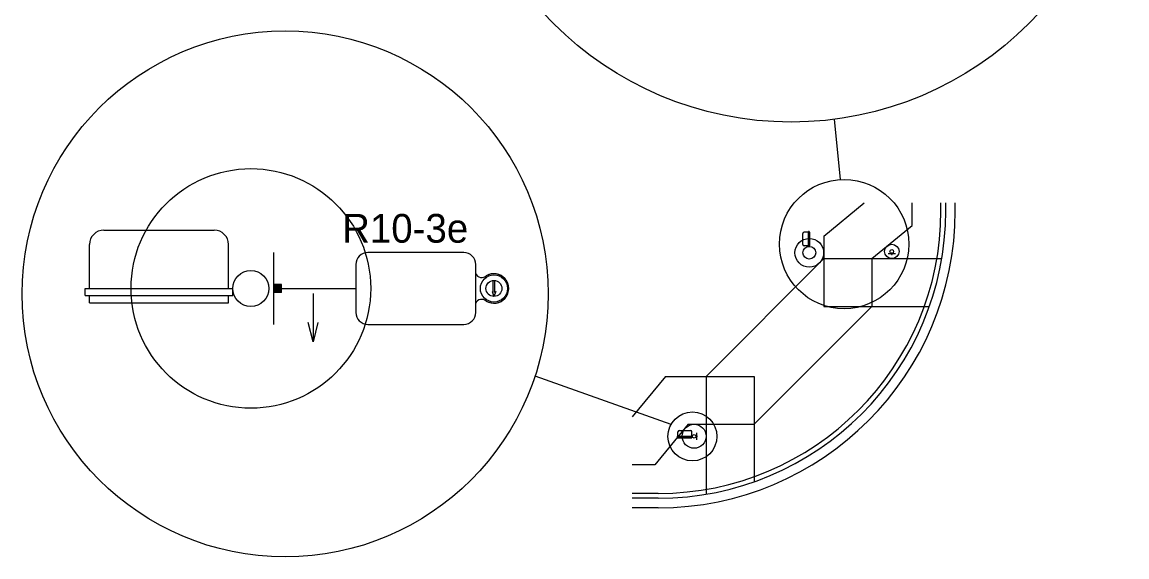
# Model space of a CAD drawing. Extents: x 1695551 to 1695718, y 544410 to 544516.
# Drawn here: x 1695643.15 to 1695671.96, y 544427.28 to 544441.23 of the extents above; entities that cross this region are included whole.
import ezdxf

# ---------------------------------------------------------------- set-up
doc = ezdxf.new("R2010")
doc.units = 0
doc.layers.add('T_Drafting', color=7, linetype='Continuous')

msp = doc.modelspace()

# ---------------------------------------------------------------- linework, layer by layer
at = {"layer": 'T_Drafting'}
for p, q in [((1695664.488, 544437.122), (1695664.339, 544438.696)), ((1695664.057, 544435.649), (1695665.107, 544436.512)), ((1695666.361, 544435.925), (1695666.361, 544436.512)), ((1695667.111, 544436.309), (1695667.111, 544436.512)), ((1695667.236, 544436.309), (1695667.236, 544436.512)), ((1695667.486, 544436.309), (1695667.486, 544436.512)), ((1695665.307, 544435.059), (1695666.361, 544435.925)), ((1695645.28, 544435.803), (1695648.155, 544435.803)), ((1695663.506, 544435.429), (1695663.506, 544435.716)), ((1695663.658, 544435.754), (1695663.543, 544435.754)), ((1695663.658, 544435.38), (1695663.658, 544435.765)), ((1695663.677, 544435.765), (1695663.658, 544435.765)), ((1695663.677, 544435.38), (1695663.677, 544435.765)), ((1695663.696, 544435.754), (1695663.677, 544435.754)), ((1695663.696, 544435.391), (1695663.696, 544435.754)), ((1695664.057, 544435.649), (1695664.057, 544433.809)), ((1695644.905, 544434.282), (1695644.905, 544435.428)), ((1695648.53, 544434.282), (1695648.53, 544435.428)), ((1695663.658, 544435.391), (1695663.543, 544435.391)), ((1695663.677, 544435.38), (1695663.658, 544435.38)), ((1695663.696, 544435.391), (1695663.677, 544435.391)), ((1695649.707, 544435.22), (1695649.707, 544433.345)), ((1695654.666, 544435.22), (1695652.162, 544435.22)), ((1695664.057, 544435.059), (1695660.986, 544431.987)), ((1695664.057, 544435.059), (1695667.131, 544435.059)), ((1695665.307, 544435.059), (1695665.307, 544433.809)), ((1695665.924, 544435.187), (1695665.737, 544435.187)), ((1695665.82, 544435.166), (1695665.82, 544435.187)), ((1695665.82, 544435.166), (1695665.841, 544435.187)), ((1695665.82, 544435.166), (1695665.84, 544435.187)), ((1695665.82, 544435.167), (1695665.84, 544435.187)), ((1695665.82, 544435.167), (1695665.84, 544435.187)), ((1695665.82, 544435.167), (1695665.839, 544435.187)), ((1695665.82, 544435.168), (1695665.839, 544435.187)), ((1695665.82, 544435.168), (1695665.839, 544435.187)), ((1695665.82, 544435.168), (1695665.838, 544435.187)), ((1695665.82, 544435.169), (1695665.838, 544435.187)), ((1695665.82, 544435.169), (1695665.838, 544435.187)), ((1695665.82, 544435.169), (1695665.837, 544435.187)), ((1695665.82, 544435.17), (1695665.837, 544435.187)), ((1695665.82, 544435.17), (1695665.837, 544435.187)), ((1695665.82, 544435.171), (1695665.836, 544435.187)), ((1695665.82, 544435.171), (1695665.836, 544435.187)), ((1695665.82, 544435.171), (1695665.835, 544435.187)), ((1695665.82, 544435.172), (1695665.835, 544435.187)), ((1695665.82, 544435.172), (1695665.835, 544435.187)), ((1695665.82, 544435.172), (1695665.834, 544435.187)), ((1695665.82, 544435.173), (1695665.834, 544435.187)), ((1695665.82, 544435.173), (1695665.834, 544435.187)), ((1695665.82, 544435.173), (1695665.833, 544435.187)), ((1695665.82, 544435.174), (1695665.833, 544435.187)), ((1695665.82, 544435.174), (1695665.833, 544435.187)), ((1695665.82, 544435.174), (1695665.832, 544435.187)), ((1695665.82, 544435.175), (1695665.832, 544435.187)), ((1695665.82, 544435.175), (1695665.832, 544435.187)), ((1695665.82, 544435.175), (1695665.831, 544435.187)), ((1695665.82, 544435.176), (1695665.831, 544435.187)), ((1695665.82, 544435.176), (1695665.831, 544435.187)), ((1695665.82, 544435.177), (1695665.83, 544435.187)), ((1695665.82, 544435.177), (1695665.83, 544435.187)), ((1695665.82, 544435.177), (1695665.829, 544435.187)), ((1695665.82, 544435.178), (1695665.829, 544435.187)), ((1695665.82, 544435.178), (1695665.829, 544435.187)), ((1695665.82, 544435.178), (1695665.828, 544435.187)), ((1695665.82, 544435.179), (1695665.828, 544435.187)), ((1695665.82, 544435.179), (1695665.828, 544435.187)), ((1695665.82, 544435.179), (1695665.827, 544435.187)), ((1695665.82, 544435.18), (1695665.827, 544435.187)), ((1695665.82, 544435.18), (1695665.827, 544435.187)), ((1695665.82, 544435.18), (1695665.826, 544435.187)), ((1695665.82, 544435.181), (1695665.826, 544435.187)), ((1695665.82, 544435.181), (1695665.826, 544435.187)), ((1695665.82, 544435.182), (1695665.825, 544435.187)), ((1695665.82, 544435.182), (1695665.825, 544435.187)), ((1695665.82, 544435.182), (1695665.824, 544435.187)), ((1695665.82, 544435.183), (1695665.824, 544435.187)), ((1695665.82, 544435.183), (1695665.824, 544435.187)), ((1695665.82, 544435.183), (1695665.823, 544435.187)), ((1695665.82, 544435.184), (1695665.823, 544435.187)), ((1695665.82, 544435.184), (1695665.823, 544435.187)), ((1695665.82, 544435.184), (1695665.822, 544435.187)), ((1695665.82, 544435.185), (1695665.822, 544435.187)), ((1695665.82, 544435.185), (1695665.822, 544435.187)), ((1695665.82, 544435.185), (1695665.821, 544435.187)), ((1695665.82, 544435.186), (1695665.821, 544435.187)), ((1695665.82, 544435.186), (1695665.821, 544435.187)), ((1695665.82, 544435.186), (1695665.82, 544435.187)), ((1695665.82, 544435.166), (1695665.841, 544435.186)), ((1695665.82, 544435.166), (1695665.841, 544435.166)), ((1695665.821, 544435.166), (1695665.841, 544435.186)), ((1695665.821, 544435.166), (1695665.841, 544435.186)), ((1695665.821, 544435.166), (1695665.841, 544435.185)), ((1695665.822, 544435.166), (1695665.841, 544435.185)), ((1695665.822, 544435.166), (1695665.841, 544435.185)), ((1695665.822, 544435.166), (1695665.841, 544435.184)), ((1695665.823, 544435.166), (1695665.841, 544435.184)), ((1695665.823, 544435.166), (1695665.841, 544435.184)), ((1695665.823, 544435.166), (1695665.841, 544435.183)), ((1695665.824, 544435.166), (1695665.841, 544435.183)), ((1695665.824, 544435.166), (1695665.841, 544435.183)), ((1695665.825, 544435.166), (1695665.841, 544435.182)), ((1695665.825, 544435.166), (1695665.841, 544435.182)), ((1695665.825, 544435.166), (1695665.841, 544435.181)), ((1695665.826, 544435.166), (1695665.841, 544435.181)), ((1695665.826, 544435.166), (1695665.841, 544435.181)), ((1695665.826, 544435.166), (1695665.841, 544435.18)), ((1695665.827, 544435.166), (1695665.841, 544435.18)), ((1695665.827, 544435.166), (1695665.841, 544435.18)), ((1695665.827, 544435.166), (1695665.841, 544435.179)), ((1695665.828, 544435.166), (1695665.841, 544435.179)), ((1695665.828, 544435.166), (1695665.841, 544435.179)), ((1695665.828, 544435.166), (1695665.841, 544435.178)), ((1695665.829, 544435.166), (1695665.841, 544435.178)), ((1695665.829, 544435.166), (1695665.841, 544435.178)), ((1695665.829, 544435.166), (1695665.841, 544435.177)), ((1695665.83, 544435.166), (1695665.841, 544435.177)), ((1695665.83, 544435.166), (1695665.841, 544435.177)), ((1695665.831, 544435.166), (1695665.841, 544435.176)), ((1695665.831, 544435.166), (1695665.841, 544435.176)), ((1695665.831, 544435.166), (1695665.841, 544435.175)), ((1695665.832, 544435.166), (1695665.841, 544435.175)), ((1695665.832, 544435.166), (1695665.841, 544435.175)), ((1695665.832, 544435.166), (1695665.841, 544435.174)), ((1695665.833, 544435.166), (1695665.841, 544435.174)), ((1695665.833, 544435.166), (1695665.841, 544435.174)), ((1695665.833, 544435.166), (1695665.841, 544435.173)), ((1695665.834, 544435.166), (1695665.841, 544435.173)), ((1695665.834, 544435.166), (1695665.841, 544435.173)), ((1695665.834, 544435.166), (1695665.841, 544435.172)), ((1695665.835, 544435.166), (1695665.841, 544435.172)), ((1695665.835, 544435.166), (1695665.841, 544435.172)), ((1695665.835, 544435.166), (1695665.841, 544435.171)), ((1695665.836, 544435.166), (1695665.841, 544435.171)), ((1695665.836, 544435.166), (1695665.841, 544435.171)), ((1695665.837, 544435.166), (1695665.841, 544435.17)), ((1695665.837, 544435.166), (1695665.841, 544435.17)), ((1695665.837, 544435.166), (1695665.841, 544435.169)), ((1695665.838, 544435.166), (1695665.841, 544435.169)), ((1695665.838, 544435.166), (1695665.841, 544435.169)), ((1695665.838, 544435.166), (1695665.841, 544435.168)), ((1695665.839, 544435.166), (1695665.841, 544435.168)), ((1695665.839, 544435.166), (1695665.841, 544435.168)), ((1695665.839, 544435.166), (1695665.841, 544435.167)), ((1695665.84, 544435.166), (1695665.841, 544435.167)), ((1695665.84, 544435.166), (1695665.841, 544435.167)), ((1695665.84, 544435.166), (1695665.841, 544435.166)), ((1695665.841, 544435.166), (1695665.841, 544435.187)), ((1695665.841, 544435.166), (1695665.841, 544435.166)), ((1695651.849, 544434.907), (1695651.849, 544433.657)), ((1695654.978, 544433.657), (1695654.978, 544434.907)), ((1695649.915, 544434.386), (1695649.707, 544434.386)), ((1695649.707, 544434.179), (1695649.914, 544434.386)), ((1695649.707, 544434.182), (1695649.911, 544434.386)), ((1695649.707, 544434.186), (1695649.907, 544434.386)), ((1695649.707, 544434.189), (1695649.904, 544434.386)), ((1695649.707, 544434.193), (1695649.9, 544434.386)), ((1695649.707, 544434.197), (1695649.897, 544434.386)), ((1695649.707, 544434.2), (1695649.893, 544434.386)), ((1695649.707, 544434.204), (1695649.89, 544434.386)), ((1695649.707, 544434.207), (1695649.886, 544434.386)), ((1695649.707, 544434.211), (1695649.883, 544434.386)), ((1695649.707, 544434.214), (1695649.879, 544434.386)), ((1695649.707, 544434.218), (1695649.876, 544434.386)), ((1695649.707, 544434.221), (1695649.872, 544434.386)), ((1695649.707, 544434.225), (1695649.869, 544434.386)), ((1695649.707, 544434.228), (1695649.865, 544434.386)), ((1695649.707, 544434.232), (1695649.861, 544434.386)), ((1695649.707, 544434.235), (1695649.858, 544434.386)), ((1695649.707, 544434.239), (1695649.854, 544434.386)), ((1695649.707, 544434.243), (1695649.851, 544434.386)), ((1695649.707, 544434.246), (1695649.847, 544434.386)), ((1695649.707, 544434.25), (1695649.844, 544434.386)), ((1695649.707, 544434.253), (1695649.84, 544434.386)), ((1695649.707, 544434.257), (1695649.837, 544434.386)), ((1695649.707, 544434.26), (1695649.833, 544434.386)), ((1695649.707, 544434.264), (1695649.83, 544434.386)), ((1695649.707, 544434.267), (1695649.826, 544434.386)), ((1695649.707, 544434.271), (1695649.823, 544434.386)), ((1695649.707, 544434.274), (1695649.819, 544434.386)), ((1695649.707, 544434.278), (1695649.815, 544434.386)), ((1695649.707, 544434.281), (1695649.812, 544434.386)), ((1695649.707, 544434.285), (1695649.808, 544434.386)), ((1695649.707, 544434.288), (1695649.805, 544434.386)), ((1695649.707, 544434.292), (1695649.801, 544434.386)), ((1695649.707, 544434.296), (1695649.798, 544434.386)), ((1695649.707, 544434.299), (1695649.794, 544434.386)), ((1695649.707, 544434.303), (1695649.791, 544434.386)), ((1695649.707, 544434.306), (1695649.787, 544434.386)), ((1695649.707, 544434.31), (1695649.784, 544434.386)), ((1695649.707, 544434.313), (1695649.78, 544434.386)), ((1695649.707, 544434.317), (1695649.777, 544434.386)), ((1695649.707, 544434.32), (1695649.773, 544434.386)), ((1695649.707, 544434.324), (1695649.77, 544434.386)), ((1695649.707, 544434.327), (1695649.766, 544434.386)), ((1695649.707, 544434.331), (1695649.762, 544434.386)), ((1695649.707, 544434.334), (1695649.759, 544434.386)), ((1695649.707, 544434.338), (1695649.755, 544434.386)), ((1695649.707, 544434.342), (1695649.752, 544434.386)), ((1695649.707, 544434.345), (1695649.748, 544434.386)), ((1695649.707, 544434.349), (1695649.745, 544434.386)), ((1695649.707, 544434.352), (1695649.741, 544434.386)), ((1695649.707, 544434.356), (1695649.738, 544434.386)), ((1695649.707, 544434.359), (1695649.734, 544434.386)), ((1695649.707, 544434.363), (1695649.731, 544434.386)), ((1695649.707, 544434.366), (1695649.727, 544434.386)), ((1695649.707, 544434.37), (1695649.724, 544434.386)), ((1695649.707, 544434.373), (1695649.72, 544434.386)), ((1695649.707, 544434.377), (1695649.716, 544434.386)), ((1695649.707, 544434.38), (1695649.713, 544434.386)), ((1695649.707, 544434.384), (1695649.709, 544434.386)), ((1695649.71, 544434.178), (1695649.915, 544434.384)), ((1695649.713, 544434.178), (1695649.915, 544434.38)), ((1695649.915, 544434.178), (1695649.915, 544434.386)), ((1695655.434, 544434.489), (1695655.472, 544434.489)), ((1695655.434, 544434.176), (1695655.434, 544434.489)), ((1695655.472, 544434.176), (1695655.472, 544434.489)), ((1695644.79, 544434.282), (1695648.644, 544434.282)), ((1695644.79, 544434.095), (1695644.79, 544434.282)), ((1695644.79, 544434.095), (1695648.644, 544434.095)), ((1695644.905, 544433.907), (1695644.905, 544434.095)), ((1695648.53, 544433.907), (1695648.53, 544434.095)), ((1695648.644, 544434.095), (1695648.644, 544434.282)), ((1695649.915, 544434.178), (1695649.707, 544434.178)), ((1695649.717, 544434.178), (1695649.915, 544434.377)), ((1695649.72, 544434.178), (1695649.915, 544434.373)), ((1695649.724, 544434.178), (1695649.915, 544434.37)), ((1695649.727, 544434.178), (1695649.915, 544434.366)), ((1695649.731, 544434.178), (1695649.915, 544434.362)), ((1695649.734, 544434.178), (1695649.915, 544434.359)), ((1695649.738, 544434.178), (1695649.915, 544434.355)), ((1695649.741, 544434.178), (1695649.915, 544434.352)), ((1695649.745, 544434.178), (1695649.915, 544434.348)), ((1695649.749, 544434.178), (1695649.915, 544434.345)), ((1695649.752, 544434.178), (1695649.915, 544434.341)), ((1695649.756, 544434.178), (1695649.915, 544434.338)), ((1695649.759, 544434.178), (1695649.915, 544434.334)), ((1695649.763, 544434.178), (1695649.915, 544434.331)), ((1695649.766, 544434.178), (1695649.915, 544434.327)), ((1695649.77, 544434.178), (1695649.915, 544434.324)), ((1695649.773, 544434.178), (1695649.915, 544434.32)), ((1695649.777, 544434.178), (1695649.915, 544434.317)), ((1695649.78, 544434.178), (1695649.915, 544434.313)), ((1695649.784, 544434.178), (1695649.915, 544434.309)), ((1695649.787, 544434.178), (1695649.915, 544434.306)), ((1695649.791, 544434.178), (1695649.915, 544434.302)), ((1695649.795, 544434.178), (1695649.915, 544434.299)), ((1695649.798, 544434.178), (1695649.915, 544434.295)), ((1695649.802, 544434.178), (1695649.915, 544434.292)), ((1695649.805, 544434.178), (1695649.915, 544434.288)), ((1695649.809, 544434.178), (1695649.915, 544434.285)), ((1695649.812, 544434.178), (1695649.915, 544434.281)), ((1695649.816, 544434.178), (1695649.915, 544434.278)), ((1695649.819, 544434.178), (1695649.915, 544434.274)), ((1695649.823, 544434.178), (1695649.915, 544434.271)), ((1695649.826, 544434.178), (1695649.915, 544434.267)), ((1695649.83, 544434.178), (1695649.915, 544434.263)), ((1695649.833, 544434.178), (1695649.915, 544434.26)), ((1695649.837, 544434.178), (1695649.915, 544434.256)), ((1695649.84, 544434.178), (1695649.915, 544434.253)), ((1695649.844, 544434.178), (1695649.915, 544434.249)), ((1695649.848, 544434.178), (1695649.915, 544434.246)), ((1695649.851, 544434.178), (1695649.915, 544434.242)), ((1695649.855, 544434.178), (1695649.915, 544434.239)), ((1695649.858, 544434.178), (1695649.915, 544434.235)), ((1695649.862, 544434.178), (1695649.915, 544434.232)), ((1695649.865, 544434.178), (1695649.915, 544434.228)), ((1695649.869, 544434.178), (1695649.915, 544434.225)), ((1695649.872, 544434.178), (1695649.915, 544434.221)), ((1695649.876, 544434.178), (1695649.915, 544434.218)), ((1695649.879, 544434.178), (1695649.915, 544434.214)), ((1695649.883, 544434.178), (1695649.915, 544434.21)), ((1695649.886, 544434.178), (1695649.915, 544434.207)), ((1695649.89, 544434.178), (1695649.915, 544434.203)), ((1695649.894, 544434.178), (1695649.915, 544434.2)), ((1695649.897, 544434.178), (1695649.915, 544434.196)), ((1695649.901, 544434.178), (1695649.915, 544434.193)), ((1695649.904, 544434.178), (1695649.915, 544434.189)), ((1695649.908, 544434.178), (1695649.915, 544434.186)), ((1695649.911, 544434.178), (1695649.915, 544434.182)), ((1695649.915, 544434.282), (1695651.849, 544434.282)), ((1695649.915, 544434.178), (1695649.915, 544434.179)), ((1695650.734, 544434.149), (1695650.734, 544432.891)), ((1695655.403, 544434.201), (1695655.453, 544434.074)), ((1695655.434, 544434.176), (1695655.403, 544434.201)), ((1695655.503, 544434.201), (1695655.453, 544434.074)), ((1695655.503, 544434.201), (1695655.472, 544434.176)), ((1695644.905, 544433.907), (1695648.53, 544433.907)), ((1695665.307, 544433.809), (1695662.236, 544430.737)), ((1695664.057, 544433.809), (1695666.807, 544433.809)), ((1695652.162, 544433.345), (1695654.666, 544433.345)), ((1695660.072, 544430.731), (1695656.524, 544431.995)), ((1695659.929, 544431.987), (1695659.062, 544430.934)), ((1695659.929, 544431.987), (1695662.236, 544431.987)), ((1695660.986, 544431.987), (1695660.986, 544428.913)), ((1695662.236, 544431.987), (1695662.236, 544429.237)), ((1695660.52, 544430.737), (1695659.653, 544429.684)), ((1695660.52, 544430.737), (1695662.236, 544430.737)), ((1695660.241, 544430.425), (1695660.627, 544430.425)), ((1695660.241, 544430.406), (1695660.241, 544430.425)), ((1695660.241, 544430.406), (1695660.627, 544430.406)), ((1695660.253, 544430.425), (1695660.253, 544430.54)), ((1695660.253, 544430.387), (1695660.253, 544430.406)), ((1695660.253, 544430.387), (1695660.615, 544430.387)), ((1695660.29, 544430.577), (1695660.578, 544430.577)), ((1695660.615, 544430.425), (1695660.615, 544430.54)), ((1695660.615, 544430.387), (1695660.615, 544430.406)), ((1695660.627, 544430.406), (1695660.627, 544430.425)), ((1695660.733, 544430.519), (1695660.733, 544430.331)), ((1695660.754, 544430.435), (1695660.733, 544430.435)), ((1695660.733, 544430.415), (1695660.754, 544430.435)), ((1695660.733, 544430.415), (1695660.754, 544430.435)), ((1695660.733, 544430.415), (1695660.754, 544430.435)), ((1695660.733, 544430.415), (1695660.753, 544430.435)), ((1695660.733, 544430.415), (1695660.753, 544430.435)), ((1695660.733, 544430.416), (1695660.753, 544430.435)), ((1695660.733, 544430.416), (1695660.752, 544430.435)), ((1695660.733, 544430.416), (1695660.752, 544430.435)), ((1695660.733, 544430.417), (1695660.751, 544430.435)), ((1695660.733, 544430.417), (1695660.751, 544430.435)), ((1695660.733, 544430.417), (1695660.751, 544430.435)), ((1695660.733, 544430.418), (1695660.75, 544430.435)), ((1695660.733, 544430.418), (1695660.75, 544430.435)), ((1695660.733, 544430.419), (1695660.75, 544430.435)), ((1695660.733, 544430.419), (1695660.749, 544430.435)), ((1695660.733, 544430.419), (1695660.749, 544430.435)), ((1695660.733, 544430.42), (1695660.749, 544430.435)), ((1695660.733, 544430.42), (1695660.748, 544430.435)), ((1695660.733, 544430.42), (1695660.748, 544430.435)), ((1695660.733, 544430.421), (1695660.748, 544430.435)), ((1695660.733, 544430.421), (1695660.747, 544430.435)), ((1695660.733, 544430.421), (1695660.747, 544430.435)), ((1695660.733, 544430.422), (1695660.747, 544430.435)), ((1695660.733, 544430.422), (1695660.746, 544430.435)), ((1695660.733, 544430.422), (1695660.746, 544430.435)), ((1695660.733, 544430.423), (1695660.745, 544430.435)), ((1695660.733, 544430.423), (1695660.745, 544430.435)), ((1695660.733, 544430.423), (1695660.745, 544430.435)), ((1695660.733, 544430.424), (1695660.744, 544430.435)), ((1695660.733, 544430.424), (1695660.744, 544430.435)), ((1695660.733, 544430.425), (1695660.744, 544430.435)), ((1695660.733, 544430.425), (1695660.743, 544430.435)), ((1695660.733, 544430.425), (1695660.743, 544430.435)), ((1695660.733, 544430.426), (1695660.743, 544430.435)), ((1695660.733, 544430.426), (1695660.742, 544430.435)), ((1695660.733, 544430.426), (1695660.742, 544430.435)), ((1695660.733, 544430.427), (1695660.742, 544430.435)), ((1695660.733, 544430.427), (1695660.741, 544430.435)), ((1695660.733, 544430.427), (1695660.741, 544430.435)), ((1695660.733, 544430.428), (1695660.741, 544430.435)), ((1695660.733, 544430.428), (1695660.74, 544430.435)), ((1695660.733, 544430.428), (1695660.74, 544430.435)), ((1695660.733, 544430.429), (1695660.739, 544430.435)), ((1695660.733, 544430.429), (1695660.739, 544430.435)), ((1695660.733, 544430.429), (1695660.739, 544430.435)), ((1695660.733, 544430.43), (1695660.738, 544430.435)), ((1695660.733, 544430.43), (1695660.738, 544430.435)), ((1695660.733, 544430.431), (1695660.738, 544430.435)), ((1695660.733, 544430.431), (1695660.737, 544430.435)), ((1695660.733, 544430.431), (1695660.737, 544430.435)), ((1695660.733, 544430.432), (1695660.737, 544430.435)), ((1695660.733, 544430.432), (1695660.736, 544430.435)), ((1695660.733, 544430.432), (1695660.736, 544430.435)), ((1695660.733, 544430.433), (1695660.736, 544430.435)), ((1695660.733, 544430.433), (1695660.735, 544430.435)), ((1695660.733, 544430.433), (1695660.735, 544430.435)), ((1695660.733, 544430.434), (1695660.735, 544430.435)), ((1695660.733, 544430.434), (1695660.734, 544430.435)), ((1695660.733, 544430.434), (1695660.734, 544430.435)), ((1695660.733, 544430.435), (1695660.733, 544430.435)), ((1695660.733, 544430.435), (1695660.733, 544430.435)), ((1695660.754, 544430.415), (1695660.733, 544430.415)), ((1695660.734, 544430.415), (1695660.754, 544430.434)), ((1695660.734, 544430.415), (1695660.754, 544430.434)), ((1695660.735, 544430.415), (1695660.754, 544430.434)), ((1695660.735, 544430.415), (1695660.754, 544430.433)), ((1695660.735, 544430.415), (1695660.754, 544430.433)), ((1695660.736, 544430.415), (1695660.754, 544430.433)), ((1695660.736, 544430.415), (1695660.754, 544430.432)), ((1695660.736, 544430.415), (1695660.754, 544430.432)), ((1695660.737, 544430.415), (1695660.754, 544430.432)), ((1695660.737, 544430.415), (1695660.754, 544430.431)), ((1695660.737, 544430.415), (1695660.754, 544430.431)), ((1695660.738, 544430.415), (1695660.754, 544430.431)), ((1695660.738, 544430.415), (1695660.754, 544430.43)), ((1695660.738, 544430.415), (1695660.754, 544430.43)), ((1695660.739, 544430.415), (1695660.754, 544430.429)), ((1695660.739, 544430.415), (1695660.754, 544430.429)), ((1695660.739, 544430.415), (1695660.754, 544430.429)), ((1695660.74, 544430.415), (1695660.754, 544430.428)), ((1695660.74, 544430.415), (1695660.754, 544430.428)), ((1695660.741, 544430.415), (1695660.754, 544430.428)), ((1695660.741, 544430.415), (1695660.754, 544430.427)), ((1695660.741, 544430.415), (1695660.754, 544430.427)), ((1695660.742, 544430.415), (1695660.754, 544430.427)), ((1695660.742, 544430.415), (1695660.754, 544430.426)), ((1695660.742, 544430.415), (1695660.754, 544430.426)), ((1695660.743, 544430.415), (1695660.754, 544430.426)), ((1695660.743, 544430.415), (1695660.754, 544430.425)), ((1695660.743, 544430.415), (1695660.754, 544430.425)), ((1695660.744, 544430.415), (1695660.754, 544430.424)), ((1695660.744, 544430.415), (1695660.754, 544430.424)), ((1695660.744, 544430.415), (1695660.754, 544430.424)), ((1695660.745, 544430.415), (1695660.754, 544430.423)), ((1695660.745, 544430.415), (1695660.754, 544430.423)), ((1695660.745, 544430.415), (1695660.754, 544430.423)), ((1695660.746, 544430.415), (1695660.754, 544430.422)), ((1695660.746, 544430.415), (1695660.754, 544430.422)), ((1695660.747, 544430.415), (1695660.754, 544430.422)), ((1695660.747, 544430.415), (1695660.754, 544430.421)), ((1695660.747, 544430.415), (1695660.754, 544430.421)), ((1695660.748, 544430.415), (1695660.754, 544430.421)), ((1695660.748, 544430.415), (1695660.754, 544430.42)), ((1695660.748, 544430.415), (1695660.754, 544430.42)), ((1695660.749, 544430.415), (1695660.754, 544430.42)), ((1695660.749, 544430.415), (1695660.754, 544430.419)), ((1695660.749, 544430.415), (1695660.754, 544430.419)), ((1695660.75, 544430.415), (1695660.754, 544430.418)), ((1695660.75, 544430.415), (1695660.754, 544430.418)), ((1695660.75, 544430.415), (1695660.754, 544430.418)), ((1695660.751, 544430.415), (1695660.754, 544430.417)), ((1695660.751, 544430.415), (1695660.754, 544430.417)), ((1695660.751, 544430.415), (1695660.754, 544430.417)), ((1695660.752, 544430.415), (1695660.754, 544430.416)), ((1695660.752, 544430.415), (1695660.754, 544430.416)), ((1695660.753, 544430.415), (1695660.754, 544430.416)), ((1695660.753, 544430.415), (1695660.754, 544430.415)), ((1695660.753, 544430.415), (1695660.754, 544430.415)), ((1695660.754, 544430.415), (1695660.754, 544430.435)), ((1695660.754, 544430.415), (1695660.754, 544430.415)), ((1695659.653, 544429.684), (1695659.062, 544429.684)), ((1695659.736, 544428.934), (1695659.062, 544428.934)), ((1695659.736, 544428.809), (1695659.062, 544428.809)), ((1695659.736, 544428.559), (1695659.062, 544428.559))]:
    msp.add_line(p, q, dxfattribs=at)
msp.add_lwpolyline([(1695650.859, 544433.391), (1695650.734, 544432.891), (1695650.609, 544433.391)], dxfattribs=at)
for centre, radius in [((1695663.205, 544447.379), 8.757), ((1695650.007, 544434.139), 6.861), ((1695649.113, 544434.282), 3.125), ((1695664.586, 544435.439), 1.686), ((1695663.677, 544435.213), 0.375), ((1695663.677, 544435.213), 0.167), ((1695665.83, 544435.247), 0.188), ((1695665.83, 544435.247), 0.0475), ((1695649.113, 544434.282), 0.469), ((1695655.453, 544434.282), 0.354), ((1695655.453, 544434.282), 0.208), ((1695660.63, 544430.422), 0.638), ((1695660.673, 544430.425), 0.312), ((1695660.673, 544430.425), 0.0469)]:
    msp.add_circle(centre, radius, dxfattribs=at)
for centre, radius, start, end in [((1695659.736, 544436.309), 7.5, 270, 0), ((1695659.736, 544436.309), 7.75, 270, 0), ((1695659.736, 544436.309), 7.375, 270, 0), ((1695645.28, 544435.428), 0.375, 90, 180), ((1695648.155, 544435.428), 0.375, 360, 90), ((1695663.543, 544435.716), 0.0375, 90, 180), ((1695663.543, 544435.429), 0.0375, 180, 270), ((1695652.162, 544434.907), 0.312, 90, 180), ((1695654.666, 544434.907), 0.312, 0, 90), ((1695655.136, 544434.742), 0.175, 205.1956, 311.8028), ((1695655.453, 544434.282), 0.385, 238.7402, 121.2598), ((1695655.453, 544434.282), 0.385, 42.5066, 121.2598), ((1695655.136, 544433.822), 0.175, 48.1972, 154.8044), ((1695655.453, 544434.282), 0.385, 238.7402, 317.4934), ((1695652.162, 544433.657), 0.312, 180, 270), ((1695654.666, 544433.657), 0.312, 270, 0), ((1695660.29, 544430.54), 0.0375, 90, 180), ((1695660.578, 544430.54), 0.0375, 360, 90)]:
    msp.add_arc(centre, radius, start, end, dxfattribs=at)

# ---------------------------------------------------------------- texts
msp.add_text('R10-3e', height=0.75, dxfattribs=at).set_placement((1695651.493, 544435.476))

doc.saveas('drawing.dxf')
